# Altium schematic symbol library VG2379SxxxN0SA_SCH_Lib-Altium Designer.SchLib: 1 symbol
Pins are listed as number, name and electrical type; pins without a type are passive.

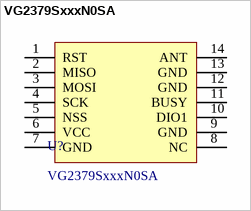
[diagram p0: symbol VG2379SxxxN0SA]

## VG2379SxxxN0SA
designator U?
footprint G237xNS1
footprint G237xNS1-TO
pins: 1 RST, 2 MISO, 3 MOSI, 4 SCK, 5 NSS, 6 VCC, 7 GND, 8 NC, 9 GND, 10 DIO1, 11 BUSY, 12 GND, 13 GND, 14 ANT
